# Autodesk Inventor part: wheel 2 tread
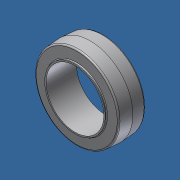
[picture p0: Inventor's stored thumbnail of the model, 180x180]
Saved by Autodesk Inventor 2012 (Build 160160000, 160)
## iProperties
Created: 2010-10
Part Number: wheel 2 tread
Document SubType Name: Modeling
Designer: Administrator
Density: 0.93 g/cm^3
Material: Rubber
Mass: 85.9208 g
Surface Area: 201.061 cm^2
Volume: 92.3879 cm^3
Author: Administrator
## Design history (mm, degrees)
feature "Base1"
body "Solid1"
